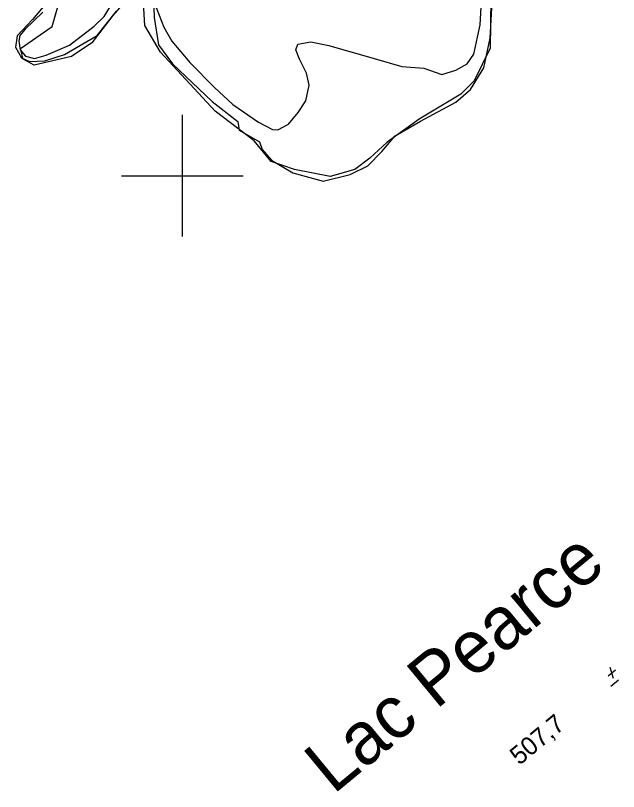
# Model space of a CAD drawing. Extents: x 347059 to 352153, y 6073752 to 6078601.
# Drawn here: x 348258.8 to 348407.6, y 6075148.1 to 6075339.5 of the extents above; entities that cross this region are included whole.
import ezdxf

# ---------------------------------------------------------------- set-up
doc = ezdxf.new("R2010")
doc.units = 0
for name, color, linetype in [('Level 2', 7, 'Continuous'), ('Level 3', 7, 'Continuous'), ('Level 4', 7, 'Continuous'), ('Level 44', 7, 'Continuous'), ('Level 61', 7, 'Continuous')]:
    doc.layers.add(name, color=color, linetype=linetype)

msp = doc.modelspace()

# ---------------------------------------------------------------- linework, layer by layer
at = {"layer": 'Level 2'}
for points in [[(348363.99, 6075324.95), (348367.47, 6075326.08), (348370.25, 6075327.58), (348371.86, 6075329.98), (348373.48, 6075337.22), (348373.87, 6075344.64)], [(348265.54, 6075340.33), (348261.23, 6075336.17), (348259.88, 6075334.64), (348259.62, 6075333.22), (348259.95, 6075331.1), (348261.27, 6075329.54), (348263.53, 6075328.91), (348266.41, 6075329.73), (348272.1, 6075332.24), (348278.25, 6075336.88), (348280.69, 6075339.33), (348282.93, 6075342.94)], [(348293.08, 6075342.54), (348295.41, 6075336.63), (348297.37, 6075333.22), (348301.85, 6075327.91), (348307.92, 6075321.82), (348312.41, 6075317.6), (348318.77, 6075313.21), (348322.23, 6075311.46), (348323.52, 6075311.34), (348326.16, 6075312.76), (348328.55, 6075315.58), (348330.45, 6075318.5), (348331.27, 6075322.39), (348330.64, 6075325.33), (348328.9, 6075328.8), (348328.01, 6075331.11), (348328.47, 6075332.44), (348331.69, 6075333.01), (348336.16, 6075332.11), (348347.3, 6075328.95), (348354.14, 6075326.98), (348359.6, 6075326.53), (348363.99, 6075324.95)]]:
    msp.add_lwpolyline(points, dxfattribs=at)
at = {"layer": 'Level 3'}
for p, q in [((348405.48, 6075178.81), (348406.31, 6075176.07)), ((348405.02, 6075176.68), (348406.82, 6075178.17)), ((348405.74, 6075174.16), (348407.59, 6075175.69))]:
    msp.add_line(p, q, dxfattribs=at)
at = {"layer": 'Level 4'}
for points in [[(348292.87, 6075343.97), (348293.04, 6075339.05), (348294.07, 6075332.3), (348297.59, 6075327.62), (348307.33, 6075318.32), (348313.63, 6075313.39), (348314.01, 6075311.22), (348319.02, 6075308.38), (348319.71, 6075306.47), (348321.98, 6075303.84), (348327.26, 6075300.77), (348334.73, 6075298.71), (348341.38, 6075300.31), (348345.78, 6075302.45), (348349.24, 6075305.99), (348352.48, 6075309.89), (348358.7, 6075313.46), (348367.49, 6075318.2), (348371.08, 6075321.32), (348374.33, 6075326.65), (348375.92, 6075333.91), (348376.59, 6075345.89)], [(348267.46, 6075343.89), (348263.02, 6075338.53), (348259.24, 6075334.55), (348258.82, 6075331.7), (348260.27, 6075329.06), (348262.25, 6075328.23), (348266.09, 6075328.34), (348270.88, 6075329.93), (348279, 6075334.59), (348283.75, 6075340.58)]]:
    msp.add_lwpolyline(points, dxfattribs=at)
at = {"layer": 'Level 44'}
for points in [[(348376.17, 6075349.75), (348375.94, 6075331.52), (348371.97, 6075323.42), (348368.7, 6075320.11), (348358.43, 6075314), (348350.5, 6075308.32), (348346.26, 6075304.36), (348342.55, 6075301.58), (348336.46, 6075299.85), (348327.65, 6075301.55), (348321.91, 6075303.55), (348317.68, 6075308.61), (348308.06, 6075315.97), (348294.57, 6075330.5), (348290.73, 6075337.09), (348290.27, 6075345.6)], [(348287.78, 6075345.33), (348282.81, 6075339.53), (348277.67, 6075332.83), (348272.67, 6075329.41), (348263.42, 6075327.28), (348260.68, 6075328.76), (348260.01, 6075331.37), (348267.83, 6075336.83), (348270.1, 6075344.6)]]:
    msp.add_lwpolyline(points, dxfattribs=at)
at = {"layer": 'Level 61'}
for p, q in [((348300, 6075285), (348300, 6075315)), ((348285, 6075300), (348315, 6075300))]:
    msp.add_line(p, q, dxfattribs=at)

# ---------------------------------------------------------------- texts
at = {"layer": 'Level 3'}
msp.add_text('  507,7', height=4.5, rotation=39.57, dxfattribs=at).set_placement((348380.55, 6075152.34))
at = {"layer": 'Level 4'}
msp.add_text('Lac Pearce', height=13, rotation=39.5818, dxfattribs=at).set_placement((348337.23, 6075147.24))

doc.saveas('drawing.dxf')
